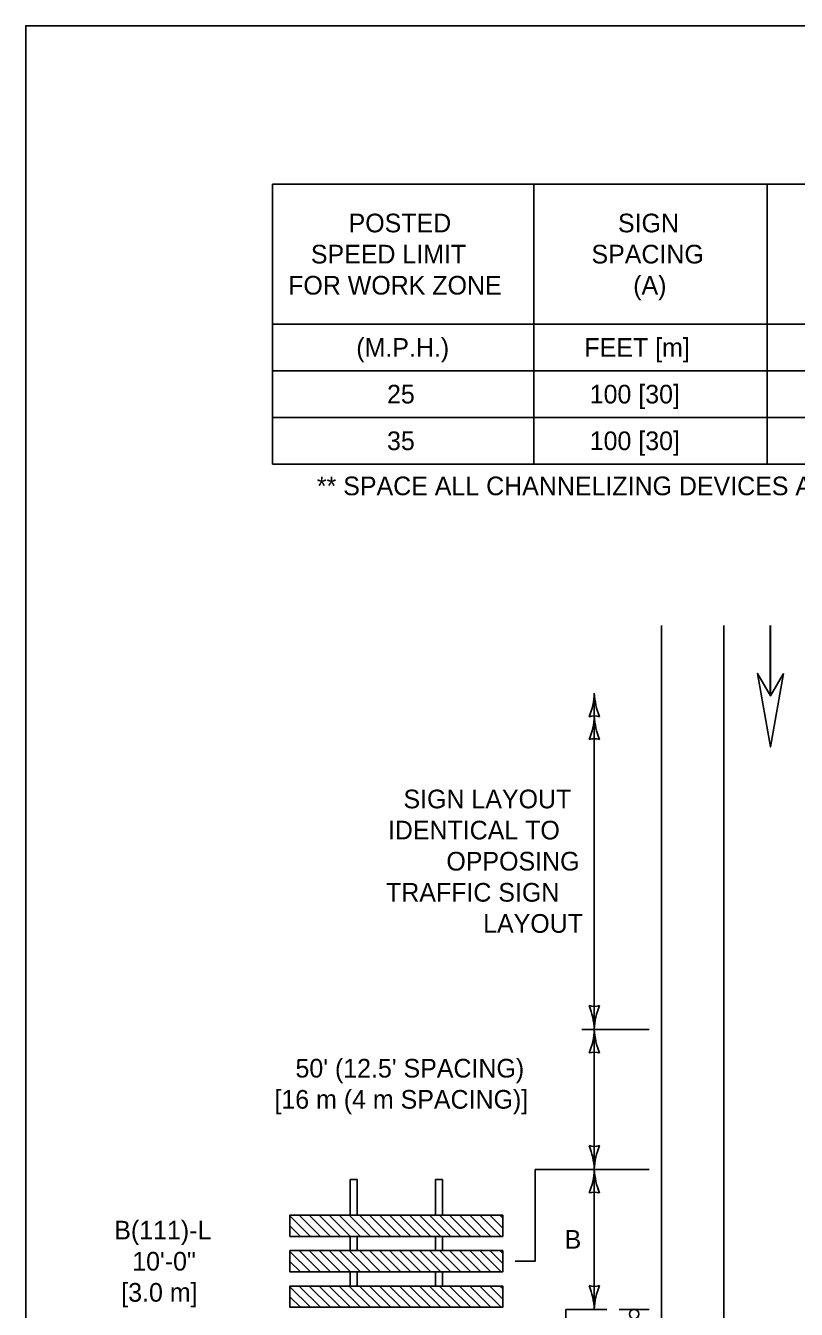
# Model space of a CAD drawing. Extents: x 49991.4 to 50021, y 49987.6 to 50011.4.
# Drawn here: x 50000.336 to 50002.813, y 50007.137 to 50011.263 of the extents above; entities that cross this region are included whole.
import ezdxf

# ---------------------------------------------------------------- set-up
doc = ezdxf.new("R2010")
doc.units = 0
for name, color, linetype in [('Level 1', 7, 'Continuous'), ('Level 2', 7, 'Continuous'), ('Level 3', 7, 'Continuous')]:
    doc.layers.add(name, color=color, linetype=linetype)

msp = doc.modelspace()

# ---------------------------------------------------------------- linework, layer by layer
at = {"layer": 'Level 1'}
for p, q in [((50002.3797, 50000.3857), (50002.3797, 50009.3344)), ((50002.5797, 50000.3857), (50002.5797, 50009.3344)), ((50002.7295, 50009.3344), (50002.7295, 50009.1085)), ((50002.7297, 50009.3344), (50002.7297, 50009.1085)), ((50001.1852, 50007.4371), (50001.2511, 50007.3712)), ((50001.1852, 50007.4371), (50001.2511, 50007.3712)), ((50001.2149, 50007.4396), (50001.2833, 50007.3712)), ((50001.2833, 50007.3712), (50001.2149, 50007.4396)), ((50001.2471, 50007.4396), (50001.3155, 50007.3712)), ((50001.2471, 50007.4396), (50001.3155, 50007.3712)), ((50001.2794, 50007.4396), (50001.3478, 50007.3712)), ((50001.3478, 50007.3712), (50001.2794, 50007.4396)), ((50001.3116, 50007.4396), (50001.38, 50007.3712)), ((50001.3116, 50007.4396), (50001.38, 50007.3712)), ((50001.3439, 50007.4396), (50001.4123, 50007.3712)), ((50001.4123, 50007.3712), (50001.3439, 50007.4396)), ((50001.3761, 50007.4396), (50001.4445, 50007.3712)), ((50001.3761, 50007.4396), (50001.4445, 50007.3712)), ((50001.4083, 50007.4396), (50001.4767, 50007.3712)), ((50001.4767, 50007.3712), (50001.4083, 50007.4396)), ((50001.4406, 50007.4396), (50001.509, 50007.3712)), ((50001.4406, 50007.4396), (50001.509, 50007.3712)), ((50001.4728, 50007.4396), (50001.5412, 50007.3712)), ((50001.5412, 50007.3712), (50001.4728, 50007.4396)), ((50001.5051, 50007.4396), (50001.5735, 50007.3712)), ((50001.5051, 50007.4396), (50001.5735, 50007.3712)), ((50001.5373, 50007.4396), (50001.6057, 50007.3712)), ((50001.6057, 50007.3712), (50001.5373, 50007.4396)), ((50001.5695, 50007.4396), (50001.6379, 50007.3712)), ((50001.5695, 50007.4396), (50001.6379, 50007.3712)), ((50001.6018, 50007.4396), (50001.6702, 50007.3712)), ((50001.6702, 50007.3712), (50001.6018, 50007.4396)), ((50001.634, 50007.4396), (50001.7024, 50007.3712)), ((50001.634, 50007.4396), (50001.7024, 50007.3712)), ((50001.6663, 50007.4396), (50001.7347, 50007.3712)), ((50001.7347, 50007.3712), (50001.6663, 50007.4396)), ((50001.6985, 50007.4396), (50001.7669, 50007.3712)), ((50001.6985, 50007.4396), (50001.7669, 50007.3712)), ((50001.7307, 50007.4396), (50001.7991, 50007.3712)), ((50001.7991, 50007.3712), (50001.7307, 50007.4396)), ((50001.763, 50007.4396), (50001.8314, 50007.3712)), ((50001.763, 50007.4396), (50001.8314, 50007.3712)), ((50001.7953, 50007.4396), (50001.8637, 50007.3712)), ((50001.8637, 50007.3712), (50001.7953, 50007.4396)), ((50001.8275, 50007.4396), (50001.8692, 50007.3979)), ((50001.8275, 50007.4396), (50001.8692, 50007.3979)), ((50001.8597, 50007.4396), (50001.8692, 50007.4301)), ((50001.8692, 50007.4301), (50001.8597, 50007.4396)), ((50001.1852, 50007.4048), (50001.2188, 50007.3712)), ((50001.2188, 50007.3712), (50001.1852, 50007.4048)), ((50001.1852, 50007.3231), (50001.2511, 50007.2572)), ((50001.1852, 50007.3231), (50001.2511, 50007.2572)), ((50001.2149, 50007.3256), (50001.2833, 50007.2572)), ((50001.2833, 50007.2572), (50001.2149, 50007.3256)), ((50001.2471, 50007.3256), (50001.3155, 50007.2572)), ((50001.2471, 50007.3256), (50001.3155, 50007.2572)), ((50001.2794, 50007.3256), (50001.3478, 50007.2572)), ((50001.3478, 50007.2572), (50001.2794, 50007.3256)), ((50001.3116, 50007.3256), (50001.38, 50007.2572)), ((50001.3116, 50007.3256), (50001.38, 50007.2572)), ((50001.3439, 50007.3256), (50001.4123, 50007.2572)), ((50001.3761, 50007.3256), (50001.4445, 50007.2572)), ((50001.4083, 50007.3256), (50001.4767, 50007.2572)), ((50001.4406, 50007.3256), (50001.509, 50007.2572)), ((50001.4728, 50007.3256), (50001.5412, 50007.2572)), ((50001.5051, 50007.3256), (50001.5735, 50007.2572)), ((50001.5373, 50007.3256), (50001.6057, 50007.2572)), ((50001.5695, 50007.3256), (50001.6379, 50007.2572)), ((50001.6018, 50007.3256), (50001.664, 50007.2634)), ((50001.634, 50007.3256), (50001.664, 50007.2956)), ((50001.6663, 50007.3256), (50001.7347, 50007.2572)), ((50001.7347, 50007.2572), (50001.6663, 50007.3256)), ((50001.6985, 50007.3256), (50001.7669, 50007.2572)), ((50001.6985, 50007.3256), (50001.7669, 50007.2572)), ((50001.7307, 50007.3256), (50001.7991, 50007.2572)), ((50001.7991, 50007.2572), (50001.7307, 50007.3256)), ((50001.763, 50007.3256), (50001.8314, 50007.2572)), ((50001.763, 50007.3256), (50001.8314, 50007.2572)), ((50001.7953, 50007.3256), (50001.8637, 50007.2572)), ((50001.8637, 50007.2572), (50001.7953, 50007.3256)), ((50001.8275, 50007.3256), (50001.8692, 50007.2839)), ((50001.8275, 50007.3256), (50001.8692, 50007.2839)), ((50001.8597, 50007.3256), (50001.8692, 50007.3161)), ((50001.8692, 50007.3161), (50001.8597, 50007.3256)), ((50001.1852, 50007.2909), (50001.2188, 50007.2572)), ((50001.2188, 50007.2572), (50001.1852, 50007.2909)), ((50001.664, 50007.2956), (50001.7024, 50007.2572)), ((50001.664, 50007.2634), (50001.6702, 50007.2572)), ((50001.4018, 50007.2572), (50001.4018, 50007.2117)), ((50001.6526, 50007.2572), (50001.6526, 50007.2117)), ((50001.1852, 50007.2091), (50001.2511, 50007.1433)), ((50001.1852, 50007.2091), (50001.2511, 50007.1433)), ((50001.2149, 50007.2117), (50001.2833, 50007.1433)), ((50001.2833, 50007.1433), (50001.2149, 50007.2117)), ((50001.2471, 50007.2117), (50001.3155, 50007.1433)), ((50001.2471, 50007.2117), (50001.3155, 50007.1433)), ((50001.2794, 50007.2117), (50001.3478, 50007.1433)), ((50001.3478, 50007.1433), (50001.2794, 50007.2117)), ((50001.3116, 50007.2117), (50001.38, 50007.1433)), ((50001.3116, 50007.2117), (50001.38, 50007.1433)), ((50001.3439, 50007.2117), (50001.4123, 50007.1433)), ((50001.3761, 50007.2117), (50001.4445, 50007.1433)), ((50001.4086, 50007.2117), (50001.477, 50007.1433)), ((50001.4408, 50007.2117), (50001.5092, 50007.1433)), ((50001.473, 50007.2117), (50001.5414, 50007.1433)), ((50001.5052, 50007.2117), (50001.5736, 50007.1433)), ((50001.5374, 50007.2117), (50001.6058, 50007.1433)), ((50001.5696, 50007.2117), (50001.638, 50007.1433)), ((50001.6018, 50007.2117), (50001.6702, 50007.1433)), ((50001.634, 50007.2117), (50001.7024, 50007.1433)), ((50001.6663, 50007.2117), (50001.7347, 50007.1433)), ((50001.7347, 50007.1433), (50001.6663, 50007.2117)), ((50001.6985, 50007.2117), (50001.7669, 50007.1433)), ((50001.6985, 50007.2117), (50001.7669, 50007.1433)), ((50001.7307, 50007.2117), (50001.7991, 50007.1433)), ((50001.7991, 50007.1433), (50001.7307, 50007.2117)), ((50001.763, 50007.2117), (50001.8314, 50007.1433)), ((50001.763, 50007.2117), (50001.8314, 50007.1433)), ((50001.7953, 50007.2117), (50001.8637, 50007.1433)), ((50001.8637, 50007.1433), (50001.7953, 50007.2117)), ((50001.8275, 50007.2117), (50001.8692, 50007.1699)), ((50001.8275, 50007.2117), (50001.8692, 50007.1699)), ((50001.8597, 50007.2117), (50001.8692, 50007.2022)), ((50001.8692, 50007.2022), (50001.8597, 50007.2117)), ((50001.1852, 50007.1769), (50001.2188, 50007.1433)), ((50001.2188, 50007.1433), (50001.1852, 50007.1769)), ((50001.3904, 50007.1433), (50001.4218, 50007.1433)), ((50001.6498, 50007.1433), (50001.4047, 50007.1433)), ((50001.6702, 50007.1433), (50001.6303, 50007.1433)), ((50002.2437, 50007.1368), (50002.3397, 50007.1368))]:
    msp.add_line(p, q, dxfattribs=at)
for points in [[(50008.6146, 50011.2628), (50000.3356, 50011.2628), (50000.3356, 50000.0624), (50008.6146, 50000.0624)], [(50002.7715, 50009.1808), (50002.7297, 50008.9443), (50002.6879, 50009.1808), (50002.7297, 50009.1086)]]:
    msp.add_lwpolyline(points, close=True, dxfattribs=at)
for points in [[(50001.4018, 50007.4397), (50001.4018, 50007.5537), (50001.379, 50007.5537), (50001.379, 50007.4397)], [(50001.6754, 50007.4397), (50001.6754, 50007.5537), (50001.6526, 50007.5537), (50001.6526, 50007.4397)], [(50001.7024, 50007.3712), (50001.8692, 50007.3712), (50001.8692, 50007.4396), (50001.1852, 50007.4396), (50001.1852, 50007.3712), (50001.3478, 50007.3712)], [(50001.1852, 50007.4048), (50001.1852, 50007.4371)], [(50001.2149, 50007.4396), (50001.2471, 50007.4396)], [(50001.2794, 50007.4396), (50001.3116, 50007.4396)], [(50001.3439, 50007.4396), (50001.3761, 50007.4396)], [(50001.4083, 50007.4396), (50001.4406, 50007.4396)], [(50001.4728, 50007.4396), (50001.5051, 50007.4396)], [(50001.5373, 50007.4396), (50001.5695, 50007.4396)], [(50001.6018, 50007.4396), (50001.634, 50007.4396)], [(50001.6663, 50007.4396), (50001.6985, 50007.4396)], [(50001.7307, 50007.4396), (50001.763, 50007.4396)], [(50001.7953, 50007.4396), (50001.8275, 50007.4396)], [(50001.8597, 50007.4396), (50001.8692, 50007.4396), (50001.8692, 50007.4301)], [(50001.8692, 50007.3979), (50001.8692, 50007.3712), (50001.8637, 50007.3712)], [(50001.2511, 50007.3712), (50001.2188, 50007.3712)], [(50001.3155, 50007.3712), (50001.2833, 50007.3712)], [(50001.38, 50007.3712), (50001.3478, 50007.3712)], [(50001.379, 50007.3712), (50001.379, 50007.3256)], [(50001.38, 50007.3712), (50001.6702, 50007.3712)], [(50001.4018, 50007.3256), (50001.4018, 50007.3712)], [(50001.4445, 50007.3712), (50001.4123, 50007.3712)], [(50001.509, 50007.3712), (50001.4767, 50007.3712)], [(50001.5735, 50007.3712), (50001.5412, 50007.3712)], [(50001.6379, 50007.3712), (50001.6057, 50007.3712)], [(50001.6526, 50007.3712), (50001.6526, 50007.3256)], [(50001.7024, 50007.3712), (50001.6702, 50007.3712)], [(50001.6754, 50007.3256), (50001.6754, 50007.3712)], [(50001.7669, 50007.3712), (50001.7347, 50007.3712)], [(50001.8314, 50007.3712), (50001.7991, 50007.3712)], [(50001.664, 50007.2572), (50001.8692, 50007.2572), (50001.8692, 50007.3256), (50001.1852, 50007.3256), (50001.1852, 50007.2572), (50001.664, 50007.2572)], [(50001.1852, 50007.2909), (50001.1852, 50007.3231)], [(50001.2149, 50007.3256), (50001.2471, 50007.3256)], [(50001.2794, 50007.3256), (50001.3116, 50007.3256)], [(50001.4445, 50007.2572), (50001.4123, 50007.2572), (50001.3439, 50007.3256), (50001.3761, 50007.3256), (50001.4445, 50007.2572)], [(50001.509, 50007.2572), (50001.4767, 50007.2572), (50001.4083, 50007.3256), (50001.4406, 50007.3256), (50001.509, 50007.2572)], [(50001.5735, 50007.2572), (50001.5412, 50007.2572), (50001.4728, 50007.3256), (50001.5051, 50007.3256), (50001.5735, 50007.2572)], [(50001.6379, 50007.2572), (50001.6057, 50007.2572), (50001.5373, 50007.3256), (50001.5695, 50007.3256), (50001.6379, 50007.2572)], [(50001.6018, 50007.3256), (50001.634, 50007.3256), (50001.664, 50007.2956), (50001.7024, 50007.2572), (50001.6754, 50007.2572), (50001.6702, 50007.2572), (50001.664, 50007.2634), (50001.6018, 50007.3256)], [(50001.6663, 50007.3256), (50001.6985, 50007.3256)], [(50001.7307, 50007.3256), (50001.763, 50007.3256)], [(50001.7953, 50007.3256), (50001.8275, 50007.3256)], [(50001.8597, 50007.3256), (50001.8692, 50007.3256), (50001.8692, 50007.3161)], [(50001.8692, 50007.2839), (50001.8692, 50007.2572), (50001.8637, 50007.2572)], [(50001.2511, 50007.2572), (50001.2188, 50007.2572)], [(50001.3155, 50007.2572), (50001.2833, 50007.2572)], [(50001.38, 50007.2572), (50001.3478, 50007.2572)], [(50001.379, 50007.2573), (50001.379, 50007.2117)], [(50001.6754, 50007.2117), (50001.6754, 50007.2572)], [(50001.7669, 50007.2572), (50001.7347, 50007.2572)], [(50001.8314, 50007.2572), (50001.7991, 50007.2572)], [(50001.664, 50007.2117), (50001.1852, 50007.2117), (50001.1852, 50007.1433), (50001.3904, 50007.1433)], [(50001.1852, 50007.1769), (50001.1852, 50007.2091)], [(50001.2149, 50007.2117), (50001.2471, 50007.2117)], [(50001.2794, 50007.2117), (50001.3116, 50007.2117)], [(50001.4445, 50007.1433), (50001.4218, 50007.1433), (50001.4123, 50007.1433), (50001.3439, 50007.2117), (50001.3761, 50007.2117), (50001.4445, 50007.1433)], [(50001.5092, 50007.1433), (50001.477, 50007.1433), (50001.4086, 50007.2117), (50001.4408, 50007.2117), (50001.5092, 50007.1433)], [(50001.5736, 50007.1433), (50001.5414, 50007.1433), (50001.473, 50007.2117), (50001.5052, 50007.2117), (50001.5736, 50007.1433)], [(50001.638, 50007.1433), (50001.6303, 50007.1433), (50001.6058, 50007.1433), (50001.5374, 50007.2117), (50001.5696, 50007.2117), (50001.638, 50007.1433)], [(50001.6018, 50007.2117), (50001.634, 50007.2117), (50001.7024, 50007.1433), (50001.6702, 50007.1433), (50001.6018, 50007.2117)], [(50001.664, 50007.1433), (50001.8692, 50007.1433), (50001.8692, 50007.2117), (50001.664, 50007.2117)], [(50001.6663, 50007.2117), (50001.6985, 50007.2117)], [(50001.7307, 50007.2117), (50001.763, 50007.2117)], [(50001.7953, 50007.2117), (50001.8275, 50007.2117)], [(50001.8597, 50007.2117), (50001.8692, 50007.2117), (50001.8692, 50007.2022)], [(50001.2511, 50007.1433), (50001.2188, 50007.1433)], [(50001.3155, 50007.1433), (50001.2833, 50007.1433)], [(50001.38, 50007.1433), (50001.3478, 50007.1433)], [(50001.7669, 50007.1433), (50001.7347, 50007.1433)], [(50001.8314, 50007.1433), (50001.7991, 50007.1433)], [(50001.8692, 50007.1699), (50001.8692, 50007.1433), (50001.8637, 50007.1433)]]:
    msp.add_lwpolyline(points, dxfattribs=at)
msp.add_circle((50002.2917, 50007.1217), 0.0152, dxfattribs=at)
at = {"layer": 'Level 2'}
for p, q in [((50001.129, 50010.7535), (50005.059, 50010.7535)), ((50001.129, 50010.7535), (50001.129, 50009.8535)), ((50001.969, 50010.7535), (50001.969, 50009.8535)), ((50002.719, 50010.7535), (50002.719, 50009.8535)), ((50001.129, 50010.3035), (50005.059, 50010.3035)), ((50001.129, 50010.1535), (50005.059, 50010.1535)), ((50001.129, 50010.0035), (50005.059, 50010.0035)), ((50001.129, 50009.8535), (50005.059, 50009.8535))]:
    msp.add_line(p, q, dxfattribs=at)
at = {"layer": 'Level 3'}
for p, q in [((50002.1637, 50008.0368), (50002.1637, 50009.1176)), ((50002.1237, 50008.0368), (50002.3397, 50008.0368)), ((50002.1637, 50007.5868), (50002.1637, 50008.0368)), ((50002.3397, 50007.5868), (50001.9734, 50007.5868)), ((50002.1637, 50007.5868), (50002.1637, 50007.1368)), ((50002.1637, 50007.5868), (50002.1637, 50007.1368)), ((50002.2037, 50007.1368), (50002.0718, 50007.1368))]:
    msp.add_line(p, q, dxfattribs=at)
for points in [[(50001.9092, 50007.2914), (50001.9734, 50007.2914), (50001.9734, 50007.5868)], [(50002.0718, 50007.1368), (50002.0718, 50006.7242), (50001.7697, 50006.7242)]]:
    msp.add_lwpolyline(points, dxfattribs=at)
for centre, radius, start, end in [((50001.9416, 50009.1267), 0.2223, 337.456, 357.6395), ((50002.3964, 50009.129), 0.233, 182.8273, 202.0772), ((50002.1637, 50008.9893), 0.0548, 72.1388, 107.8612), ((50001.9416, 50009.0533), 0.2223, 337.456, 357.6395), ((50002.3964, 50009.0556), 0.233, 182.8273, 202.0772), ((50002.1637, 50008.9159), 0.0548, 72.1388, 107.8612), ((50002.1637, 50008.1651), 0.0548, 252.1388, 287.8612), ((50001.931, 50008.0253), 0.233, 2.8273, 22.0772), ((50002.3858, 50008.0277), 0.2223, 157.456, 177.6395), ((50001.9416, 50008.046), 0.2223, 337.456, 357.6395), ((50002.3964, 50008.0483), 0.233, 182.8273, 202.0772), ((50002.1637, 50007.9086), 0.0548, 72.1388, 107.8612), ((50002.1637, 50007.7151), 0.0548, 252.1388, 287.8612), ((50001.931, 50007.5753), 0.233, 2.8273, 22.0772), ((50002.3858, 50007.5777), 0.2223, 157.456, 177.6395), ((50001.9416, 50007.596), 0.2223, 337.456, 357.6395), ((50002.3964, 50007.5983), 0.233, 182.8273, 202.0772), ((50002.1637, 50007.4586), 0.0548, 72.1388, 107.8612), ((50002.1637, 50007.2651), 0.0548, 252.1388, 287.8612), ((50001.931, 50007.1253), 0.233, 2.8273, 22.0772), ((50002.3858, 50007.1277), 0.2223, 157.456, 177.6395)]:
    msp.add_arc(centre, radius, start, end, dxfattribs=at)

# ---------------------------------------------------------------- texts
at = {"layer": 'Level 2'}
for s, p in [('POSTED', (50001.3737, 50010.5985)), ('SIGN', (50002.2397, 50010.5985)), ('SPEED LIMIT', (50001.2524, 50010.4985)), ('SPACING', (50002.1546, 50010.4985)), ('FOR WORK ZONE', (50001.1794, 50010.3985)), ('(A)', (50002.2887, 50010.3985)), ('(M.P.H.)', (50001.3984, 50010.1985)), ('FEET [m]', (50002.1318, 50010.1985)), ('25', (50001.4972, 50010.0485)), ('100 [30]', (50002.1489, 50010.0485)), ('35', (50001.4973, 50009.8985)), ('100 [30]', (50002.1489, 50009.8985)), ('** SPACE ALL CHANNELIZING DEVICES AT "G" UNLESS OTHERWISE NOTED.', (50001.2718, 50009.7535)), ('SIGN LAYOUT', (50001.5502, 50008.7472)), ('IDENTICAL TO', (50001.5, 50008.6472)), ('OPPOSING', (50001.6881, 50008.5472)), ('TRAFFIC SIGN', (50001.4941, 50008.4472)), ('LAYOUT', (50001.8062, 50008.3472)), ("50' (12.5' SPACING)", (50001.203, 50007.8818)), ('[16 m (4 m SPACING)]', (50001.1353, 50007.7818)), ('B(111)-L', (50000.6204, 50007.3614)), ('B', (50002.0682, 50007.3318)), ('10\'-0"', (50000.6782, 50007.2614)), ('[3.0 m]', (50000.6429, 50007.1614))]:
    msp.add_text(s, height=0.06, dxfattribs=at).set_placement(p)

doc.saveas('drawing.dxf')
